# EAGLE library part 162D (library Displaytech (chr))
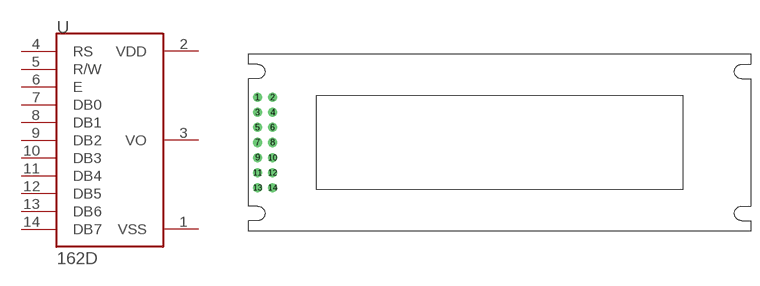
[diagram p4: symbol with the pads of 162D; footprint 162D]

Designator prefix -

## 162D  [162D]
1  VSS  pwr
2  VDD  pwr
3  VO  in
4  RS
5  R/W
6  E
7  DB0
8  DB1
9  DB2
10  DB3
11  DB4
12  DB5
13  DB6
14  DB7

## Footprint 162D (pad centres in mm)
drill 1.016 round: 1 0,0; 2 2.54,0; 3 0,-2.54; 4 2.54,-2.54; 5 0,-5.08; 6 2.54,-5.08; 7 0,-7.62; 8 2.54,-7.62; 9 0,-10.16; 10 2.54,-10.16; 11 0,-12.7; 12 2.54,-12.7; 13 0,-15.24; 14 2.54,-15.24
